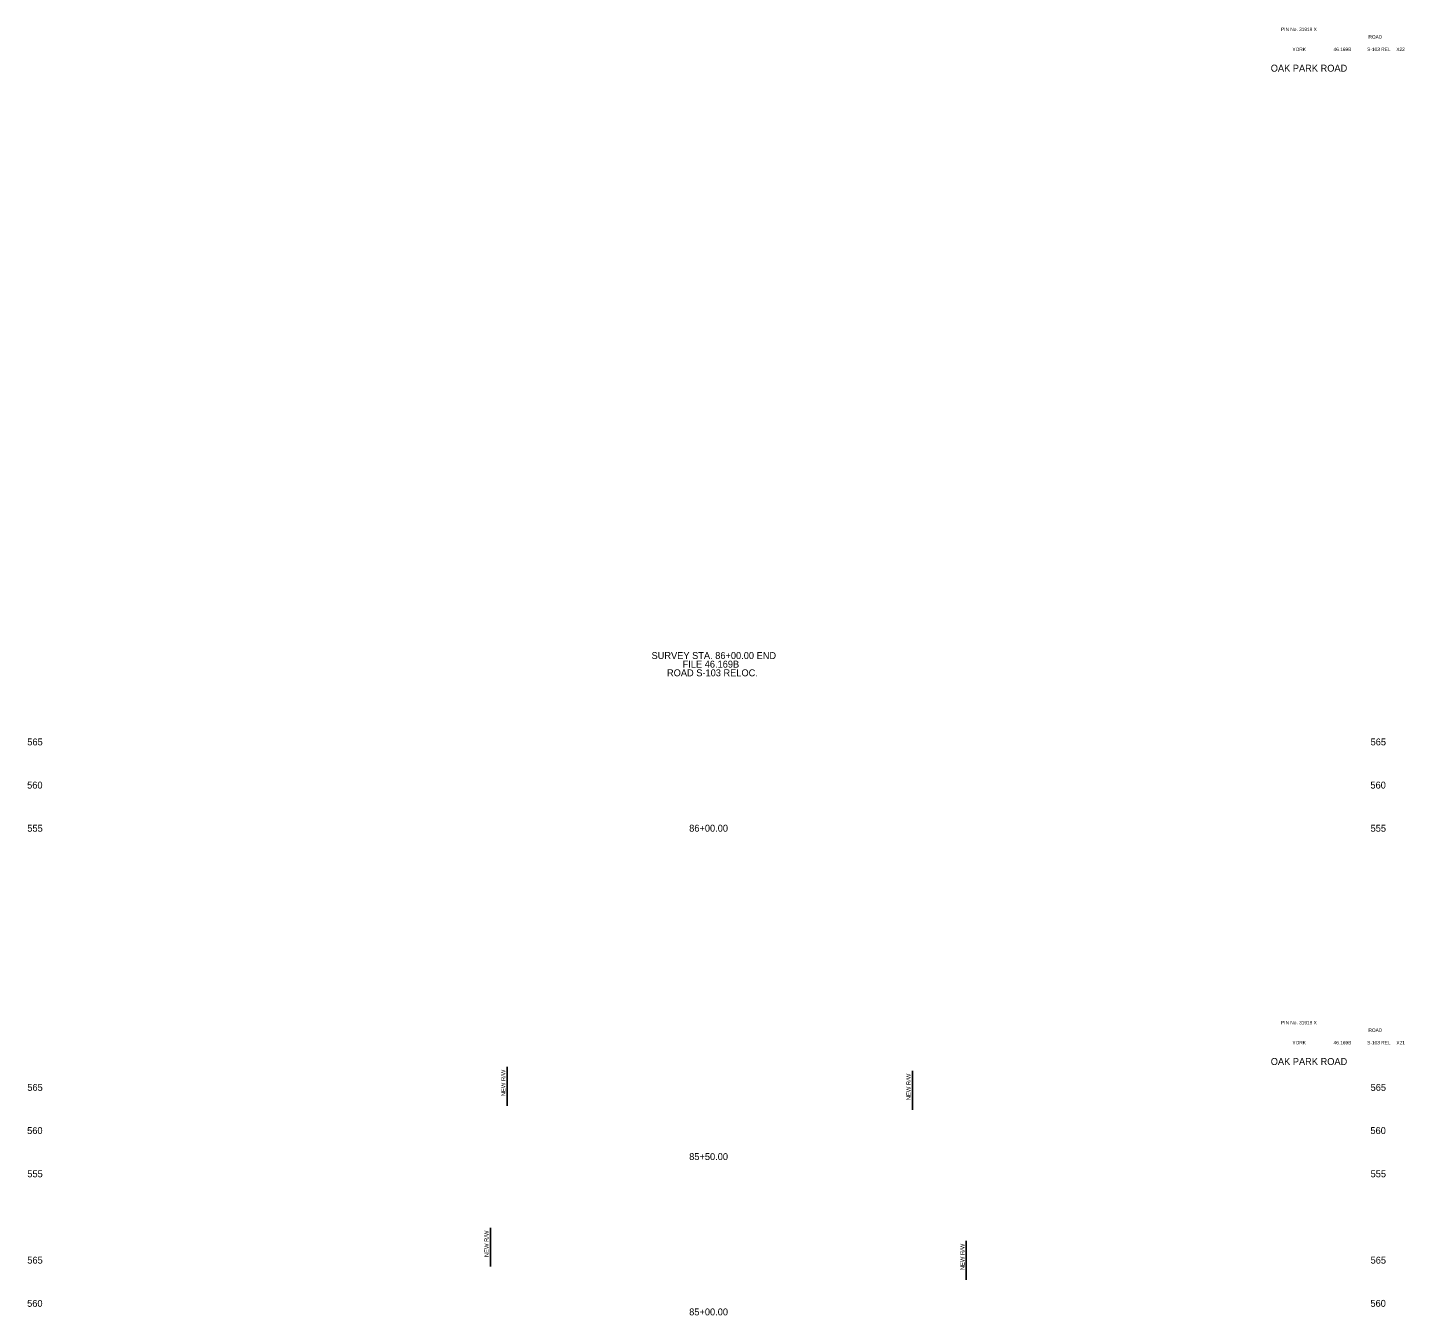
# Model space of a CAD drawing. Extents: x 1001 to 1161, y 1005 to 3518.
# Drawn here: x 1001.2 to 1160.6, y 3369.1 to 3518.2 of the extents above; entities that cross this region are included whole.
import ezdxf

# ---------------------------------------------------------------- set-up
doc = ezdxf.new("R2010")
doc.units = 0
for name, color, linetype in [('RD_SHT_TX', 7, 'Continuous'), ('RD_XS_NewRW', 7, 'Continuous'), ('RD_XS_TX_Elev_EX', 7, 'Continuous'), ('RD_XS_TX_Notes', 7, 'Continuous'), ('RD_XS_TX_Station', 7, 'Continuous')]:
    doc.layers.add(name, color=color, linetype=linetype)

msp = doc.modelspace()

# ---------------------------------------------------------------- linework, layer by layer
at = {"layer": 'RD_XS_NewRW'}
for p, q in [((1056.71, 3397.88), (1056.71, 3393.38)), ((1103.62, 3397.42), (1103.62, 3392.92)), ((1054.77, 3379.26), (1054.77, 3374.76)), ((1109.85, 3377.74), (1109.85, 3373.24))]:
    msp.add_line(p, q, dxfattribs=at)

# ---------------------------------------------------------------- texts
at = {"layer": 'RD_SHT_TX'}
for s, height, p in [('PIN No. 31919 X', 0.4, (1146.29, 3517.8)), ('ROAD', 0.4, (1156.41, 3516.93)), ('YORK', 0.4, (1147.61, 3515.48)), ('46.169B', 0.4, (1152.37, 3515.48)), ('S-103 REL', 0.4, (1156.26, 3515.48)), ('X22', 0.4, (1159.63, 3515.48)), ('OAK PARK ROAD', 0.8, (1145.1, 3513.1)), ('PIN No. 31919 X', 0.4, (1146.29, 3402.8)), ('ROAD', 0.4, (1156.41, 3401.93)), ('YORK', 0.4, (1147.61, 3400.48)), ('46.169B', 0.4, (1152.37, 3400.48)), ('S-103 REL', 0.4, (1156.26, 3400.48)), ('X21', 0.4, (1159.65, 3400.48)), ('OAK PARK ROAD', 0.8, (1145.1, 3398.1))]:
    msp.add_text(s, height=height, dxfattribs=at).set_placement(p)
at = {"layer": 'RD_XS_NewRW'}
for p in [(1056.51, 3394.48), (1103.42, 3394.02), (1054.57, 3375.86), (1109.65, 3374.34)]:
    msp.add_text('NEW R/W ', height=0.488, rotation=90, dxfattribs=at).set_placement(p)
at = {"layer": 'RD_XS_TX_Elev_EX'}
for s, p in [('565', (1001.16, 3435.1)), ('565', (1156.66, 3435.1)), ('560', (1001.14, 3430.1)), ('560', (1156.64, 3430.1)), ('555', (1001.16, 3425.1)), ('555', (1156.66, 3425.1)), ('565', (1001.16, 3395.1)), ('565', (1156.66, 3395.1)), ('560', (1001.14, 3390.1)), ('560', (1156.64, 3390.1)), ('555', (1001.16, 3385.1)), ('555', (1156.66, 3385.1)), ('565', (1001.16, 3375.1)), ('565', (1156.66, 3375.1)), ('560', (1001.14, 3370.1)), ('560', (1156.64, 3370.1))]:
    msp.add_text(s, height=0.8, dxfattribs=at).set_placement(p)
at = {"layer": 'RD_XS_TX_Notes'}
for s, p in [('SURVEY STA. 86+00.00 END', (1073.42, 3445.1)), ('FILE 46.169B', (1077.02, 3444.1)), ('ROAD S-103 RELOC.', (1075.21, 3443.1))]:
    msp.add_text(s, height=0.8, dxfattribs=at).set_placement(p)
at = {"layer": 'RD_XS_TX_Station'}
for s, p in [('86+00.00', (1077.78, 3425.11)), ('85+50.00', (1077.78, 3387.09)), ('85+00.00', (1077.78, 3369.11))]:
    msp.add_text(s, height=0.8, dxfattribs=at).set_placement(p)

doc.saveas('drawing.dxf')
